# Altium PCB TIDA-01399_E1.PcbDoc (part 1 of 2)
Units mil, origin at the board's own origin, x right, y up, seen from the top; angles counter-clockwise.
Board outline 5937.01 x 6299.21 mil, 4 copper layers (Top Layer, MidLayer1, MidLayer2, Bottom Layer), stack 61.2 mil thick; 192 components, 137 nets, 411 pads, 57 vias.
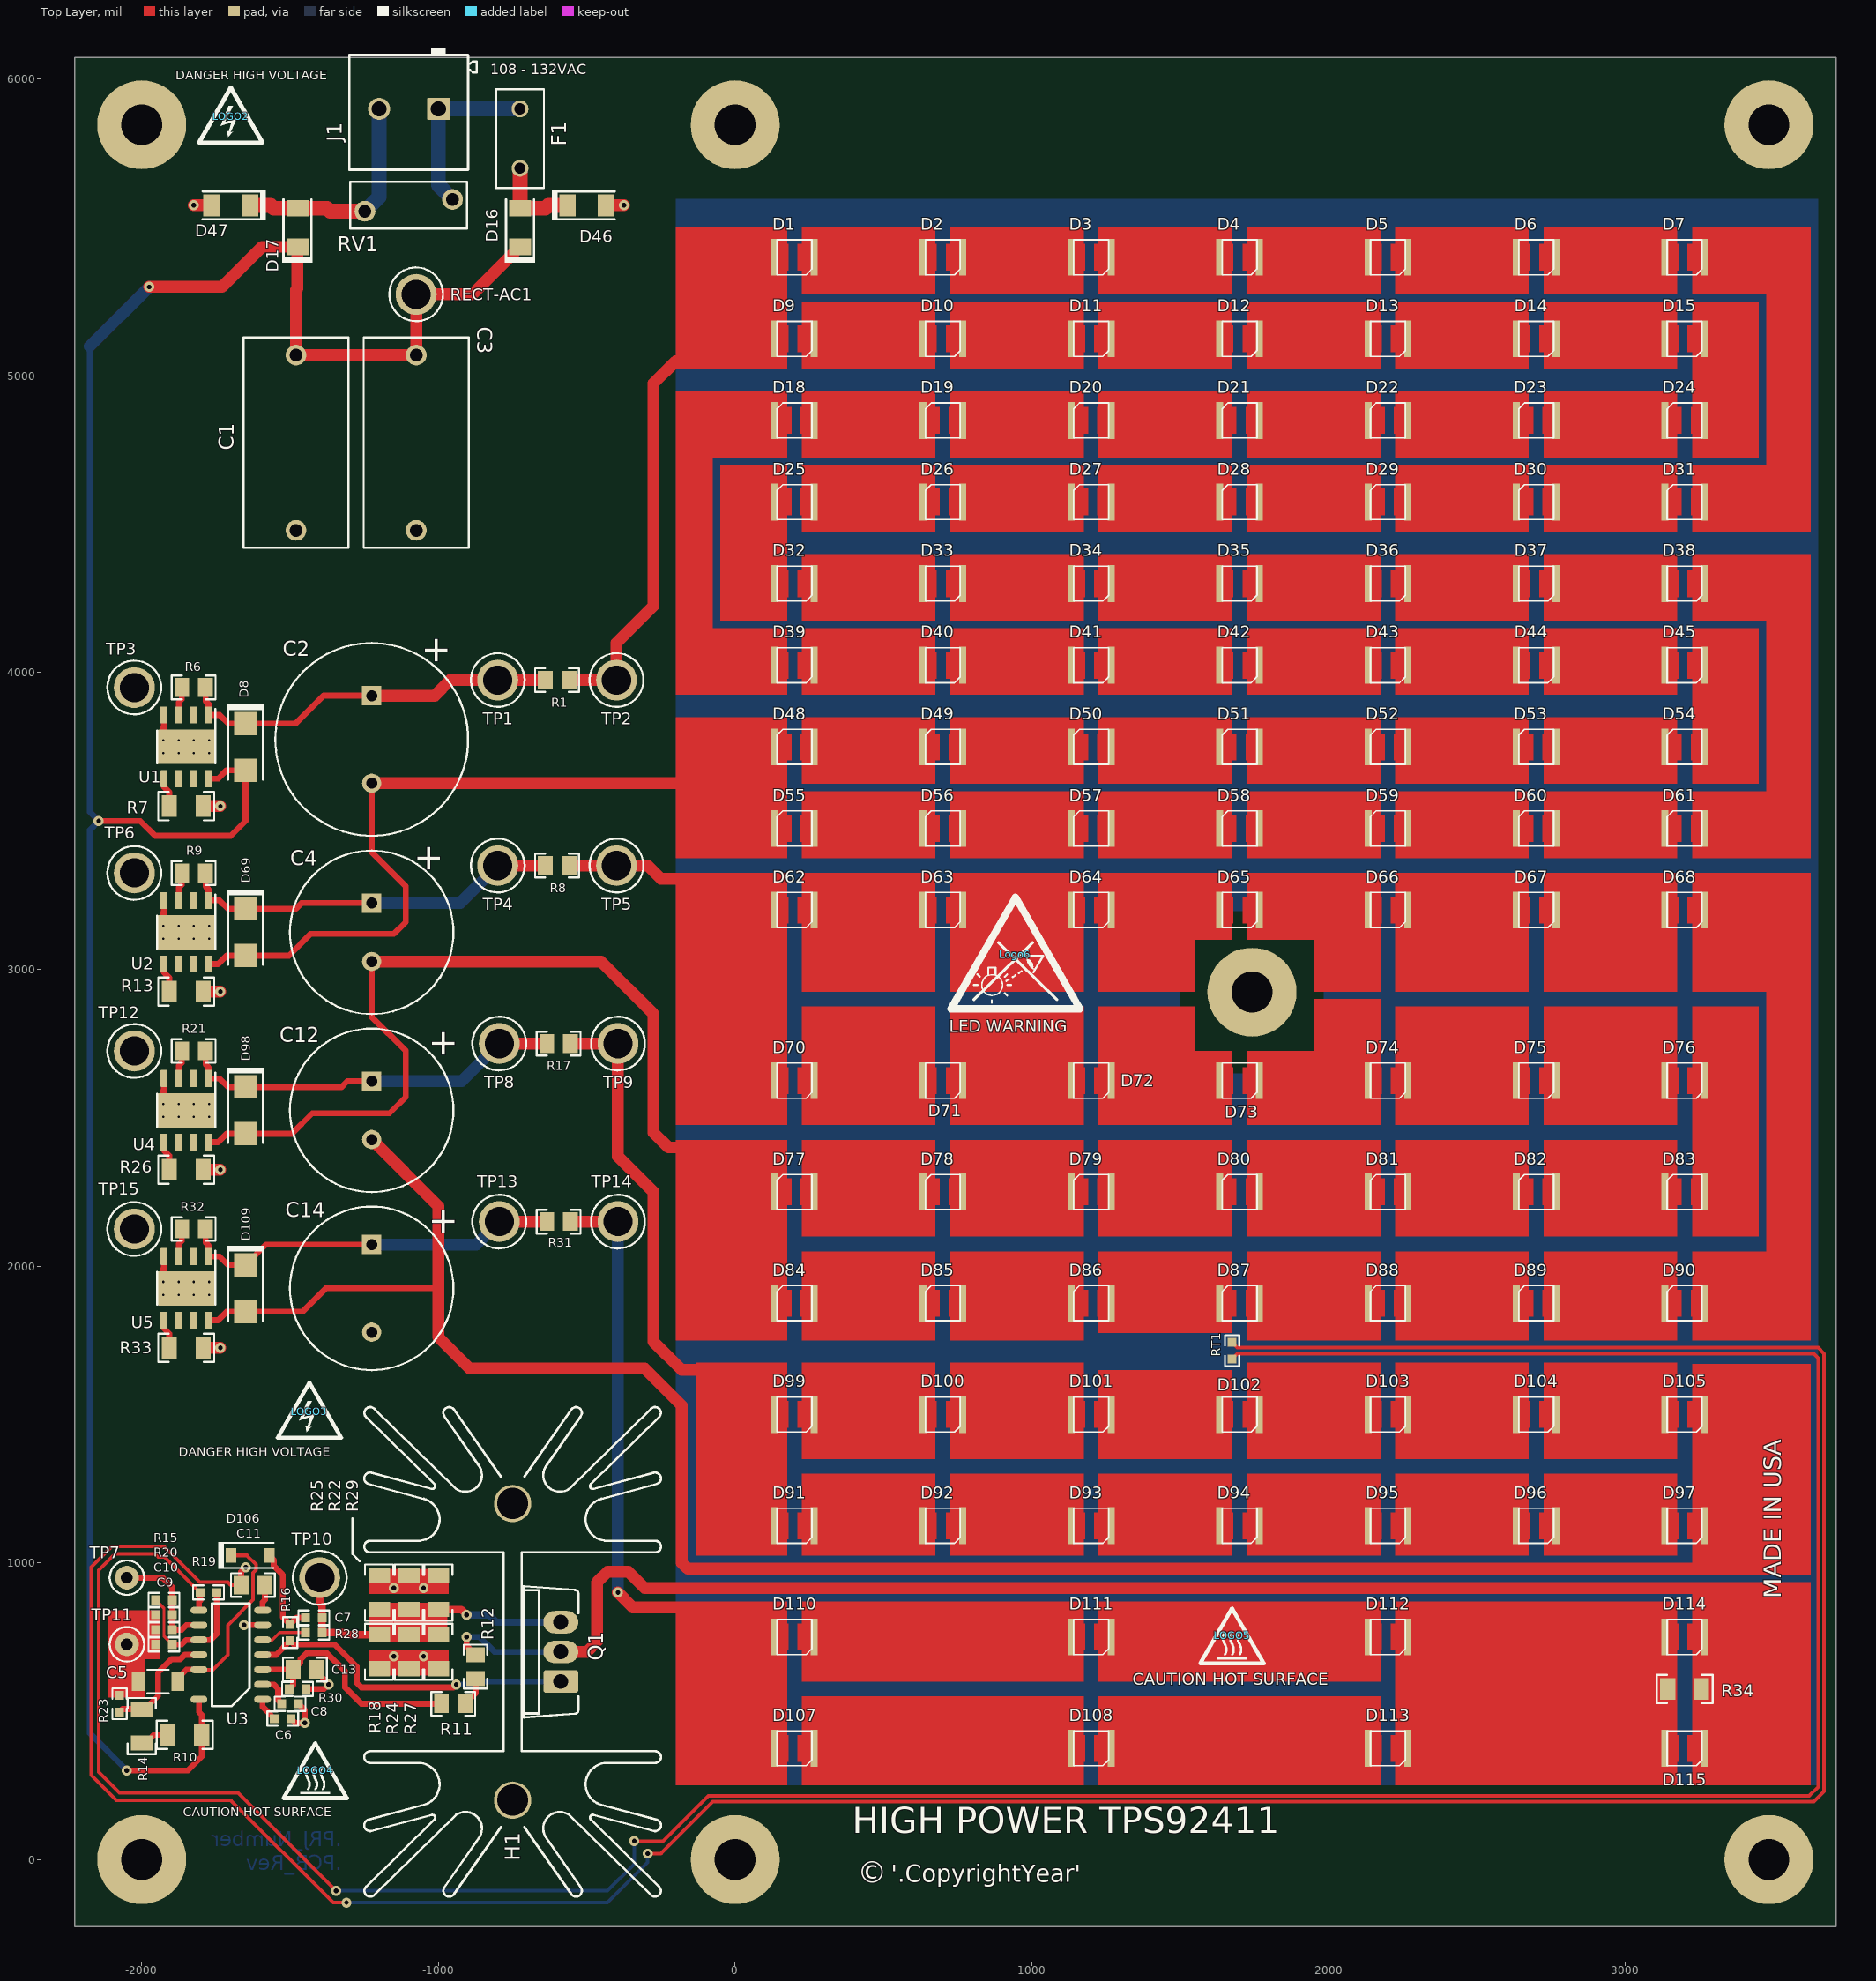
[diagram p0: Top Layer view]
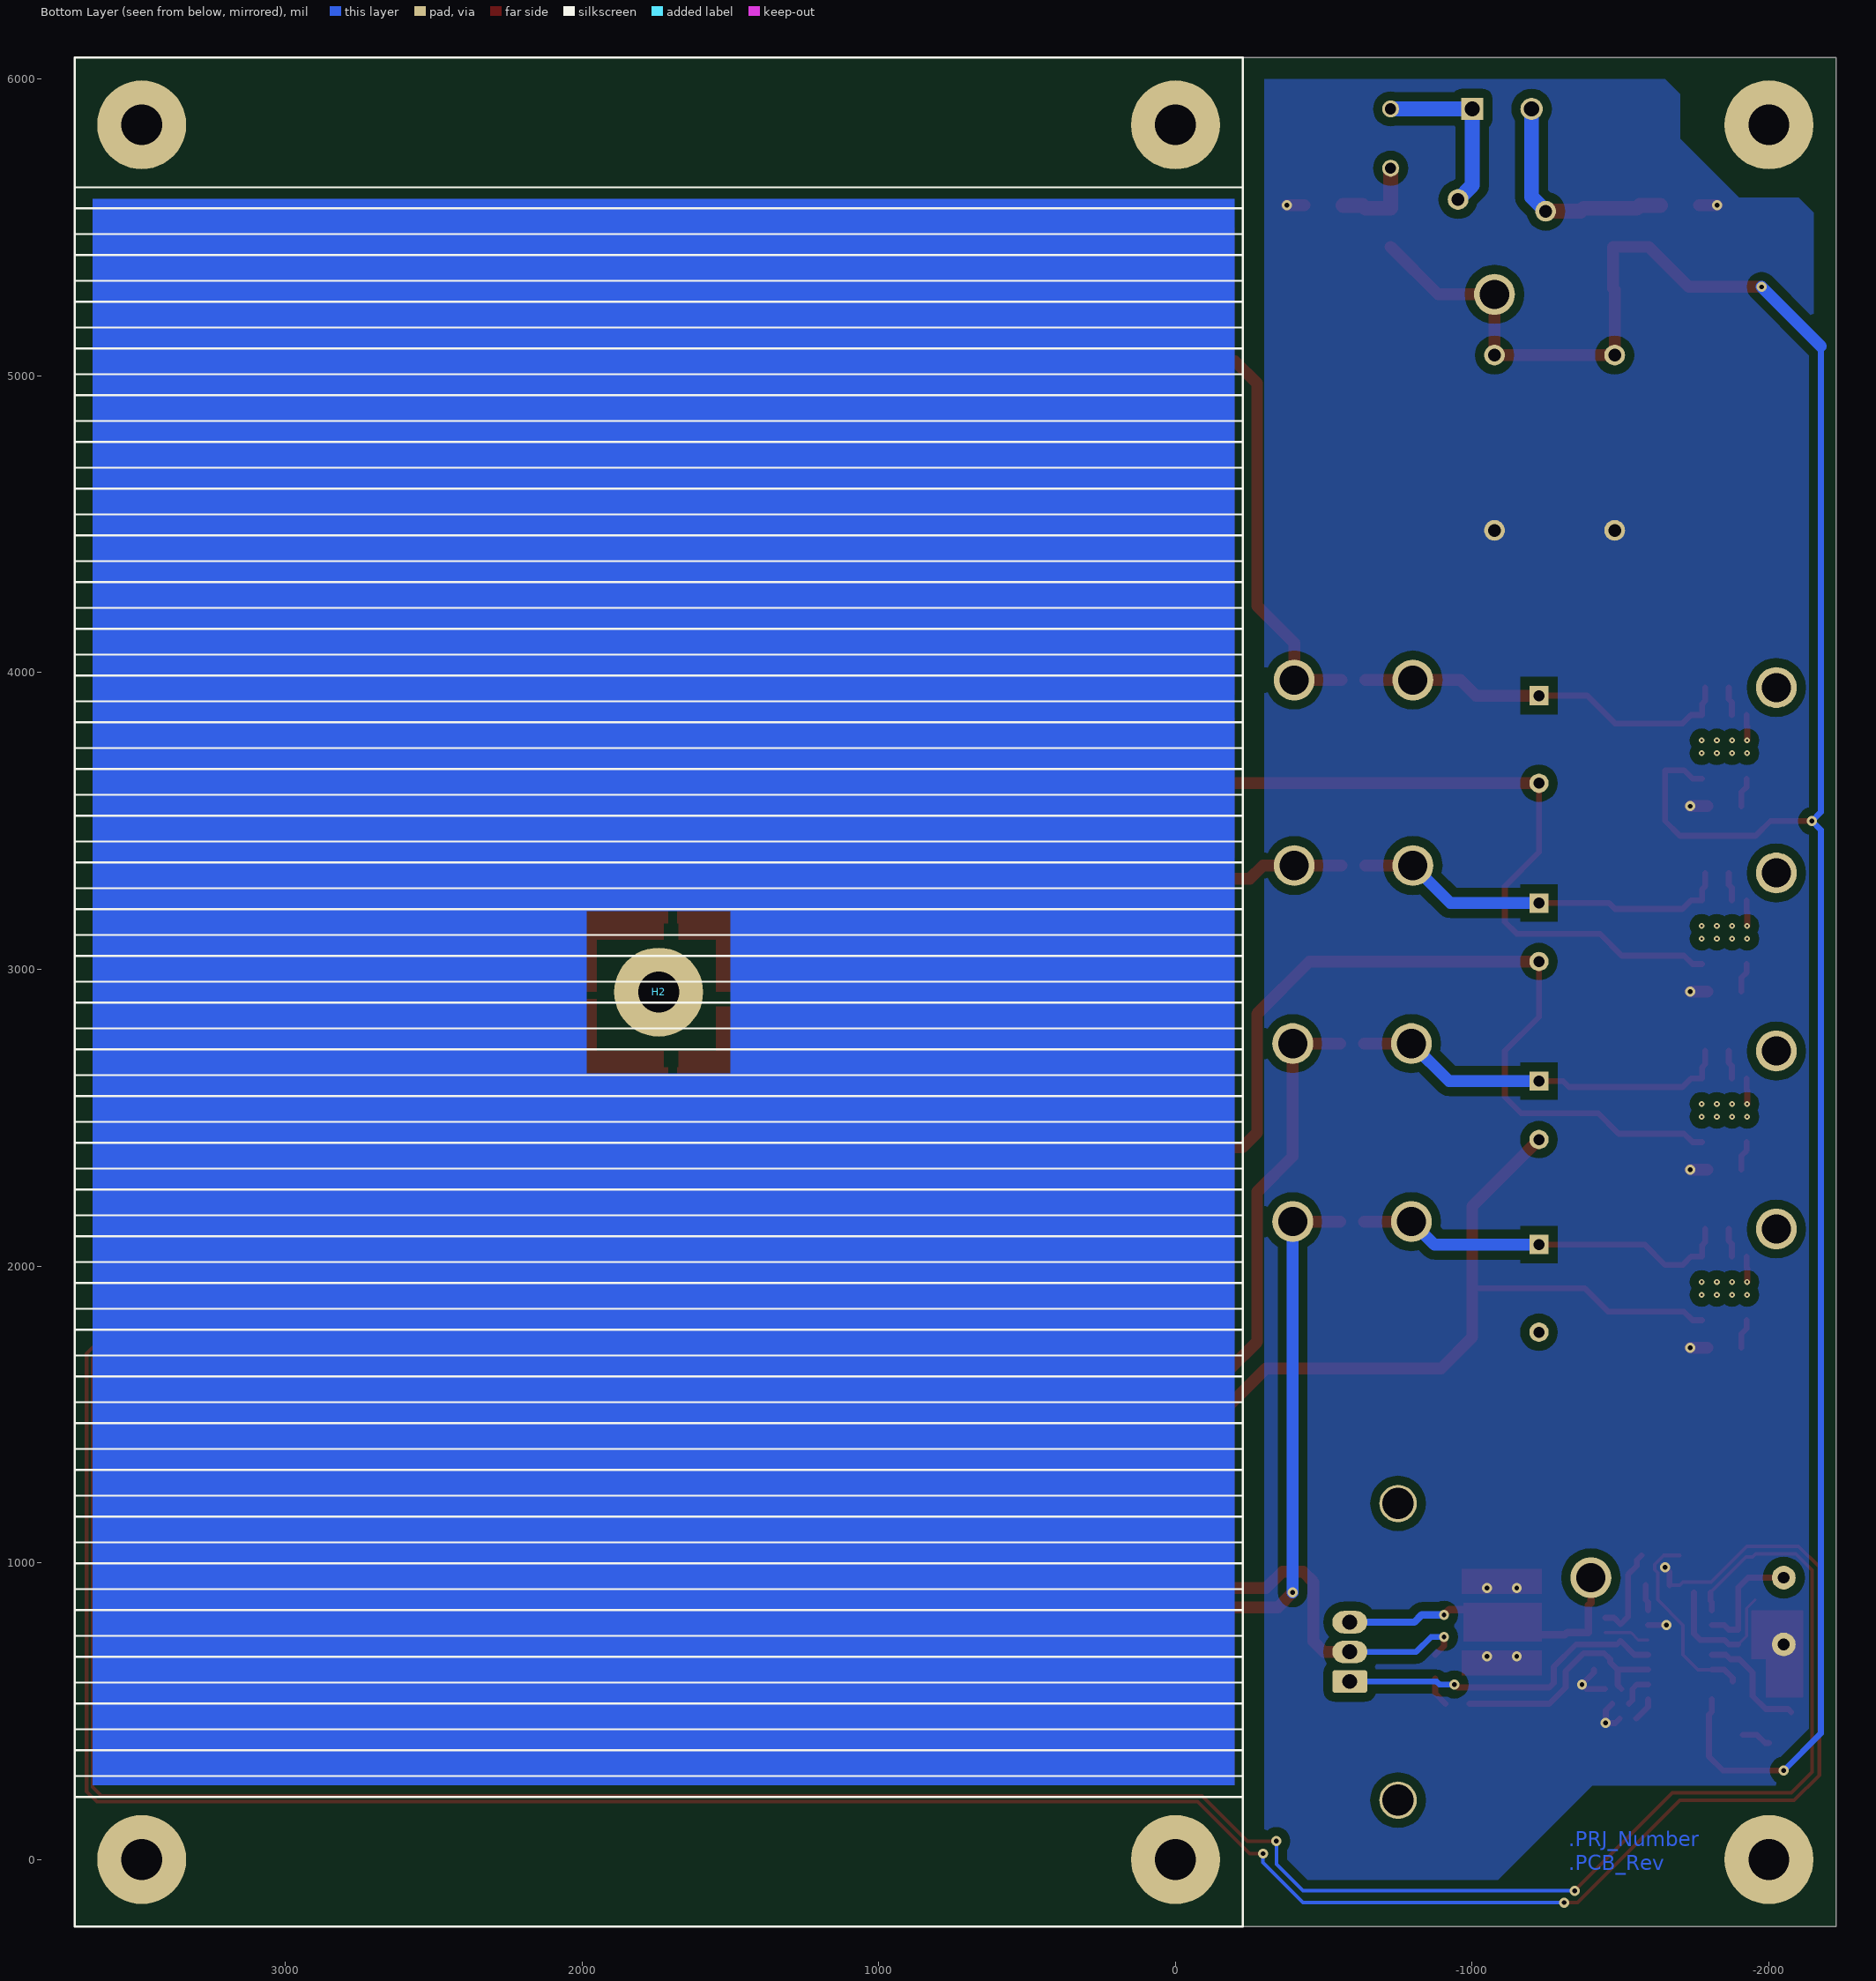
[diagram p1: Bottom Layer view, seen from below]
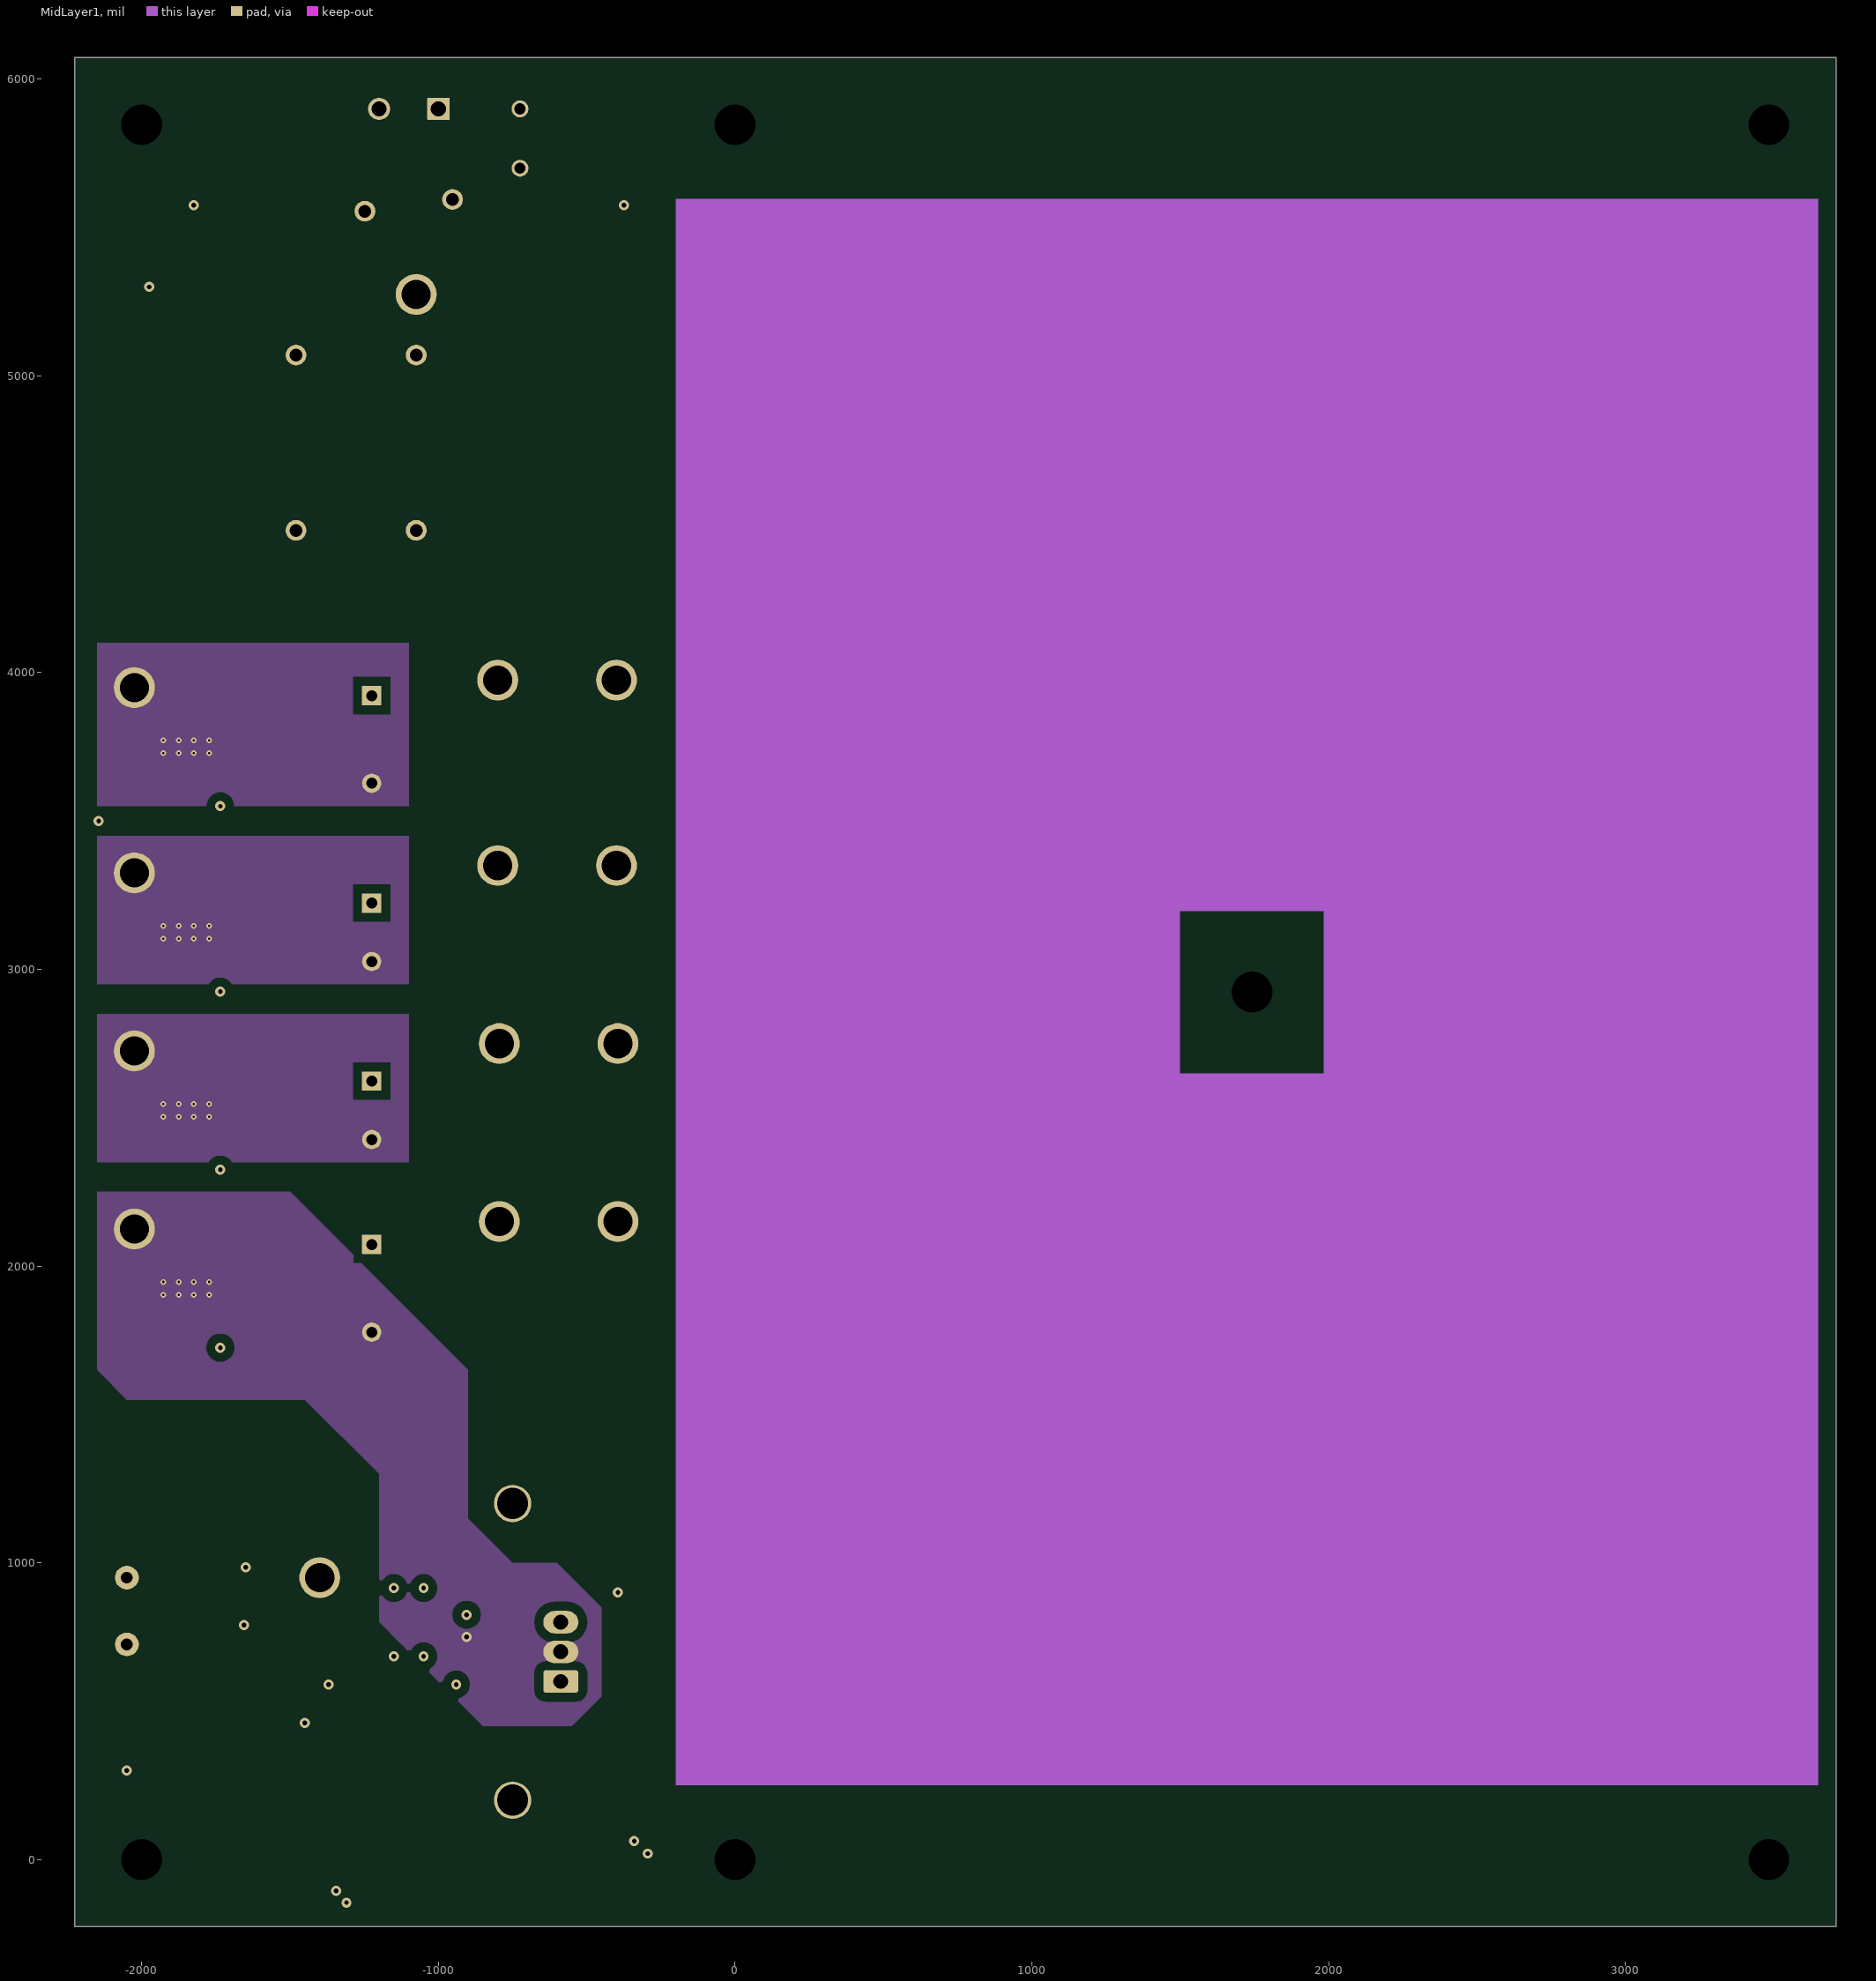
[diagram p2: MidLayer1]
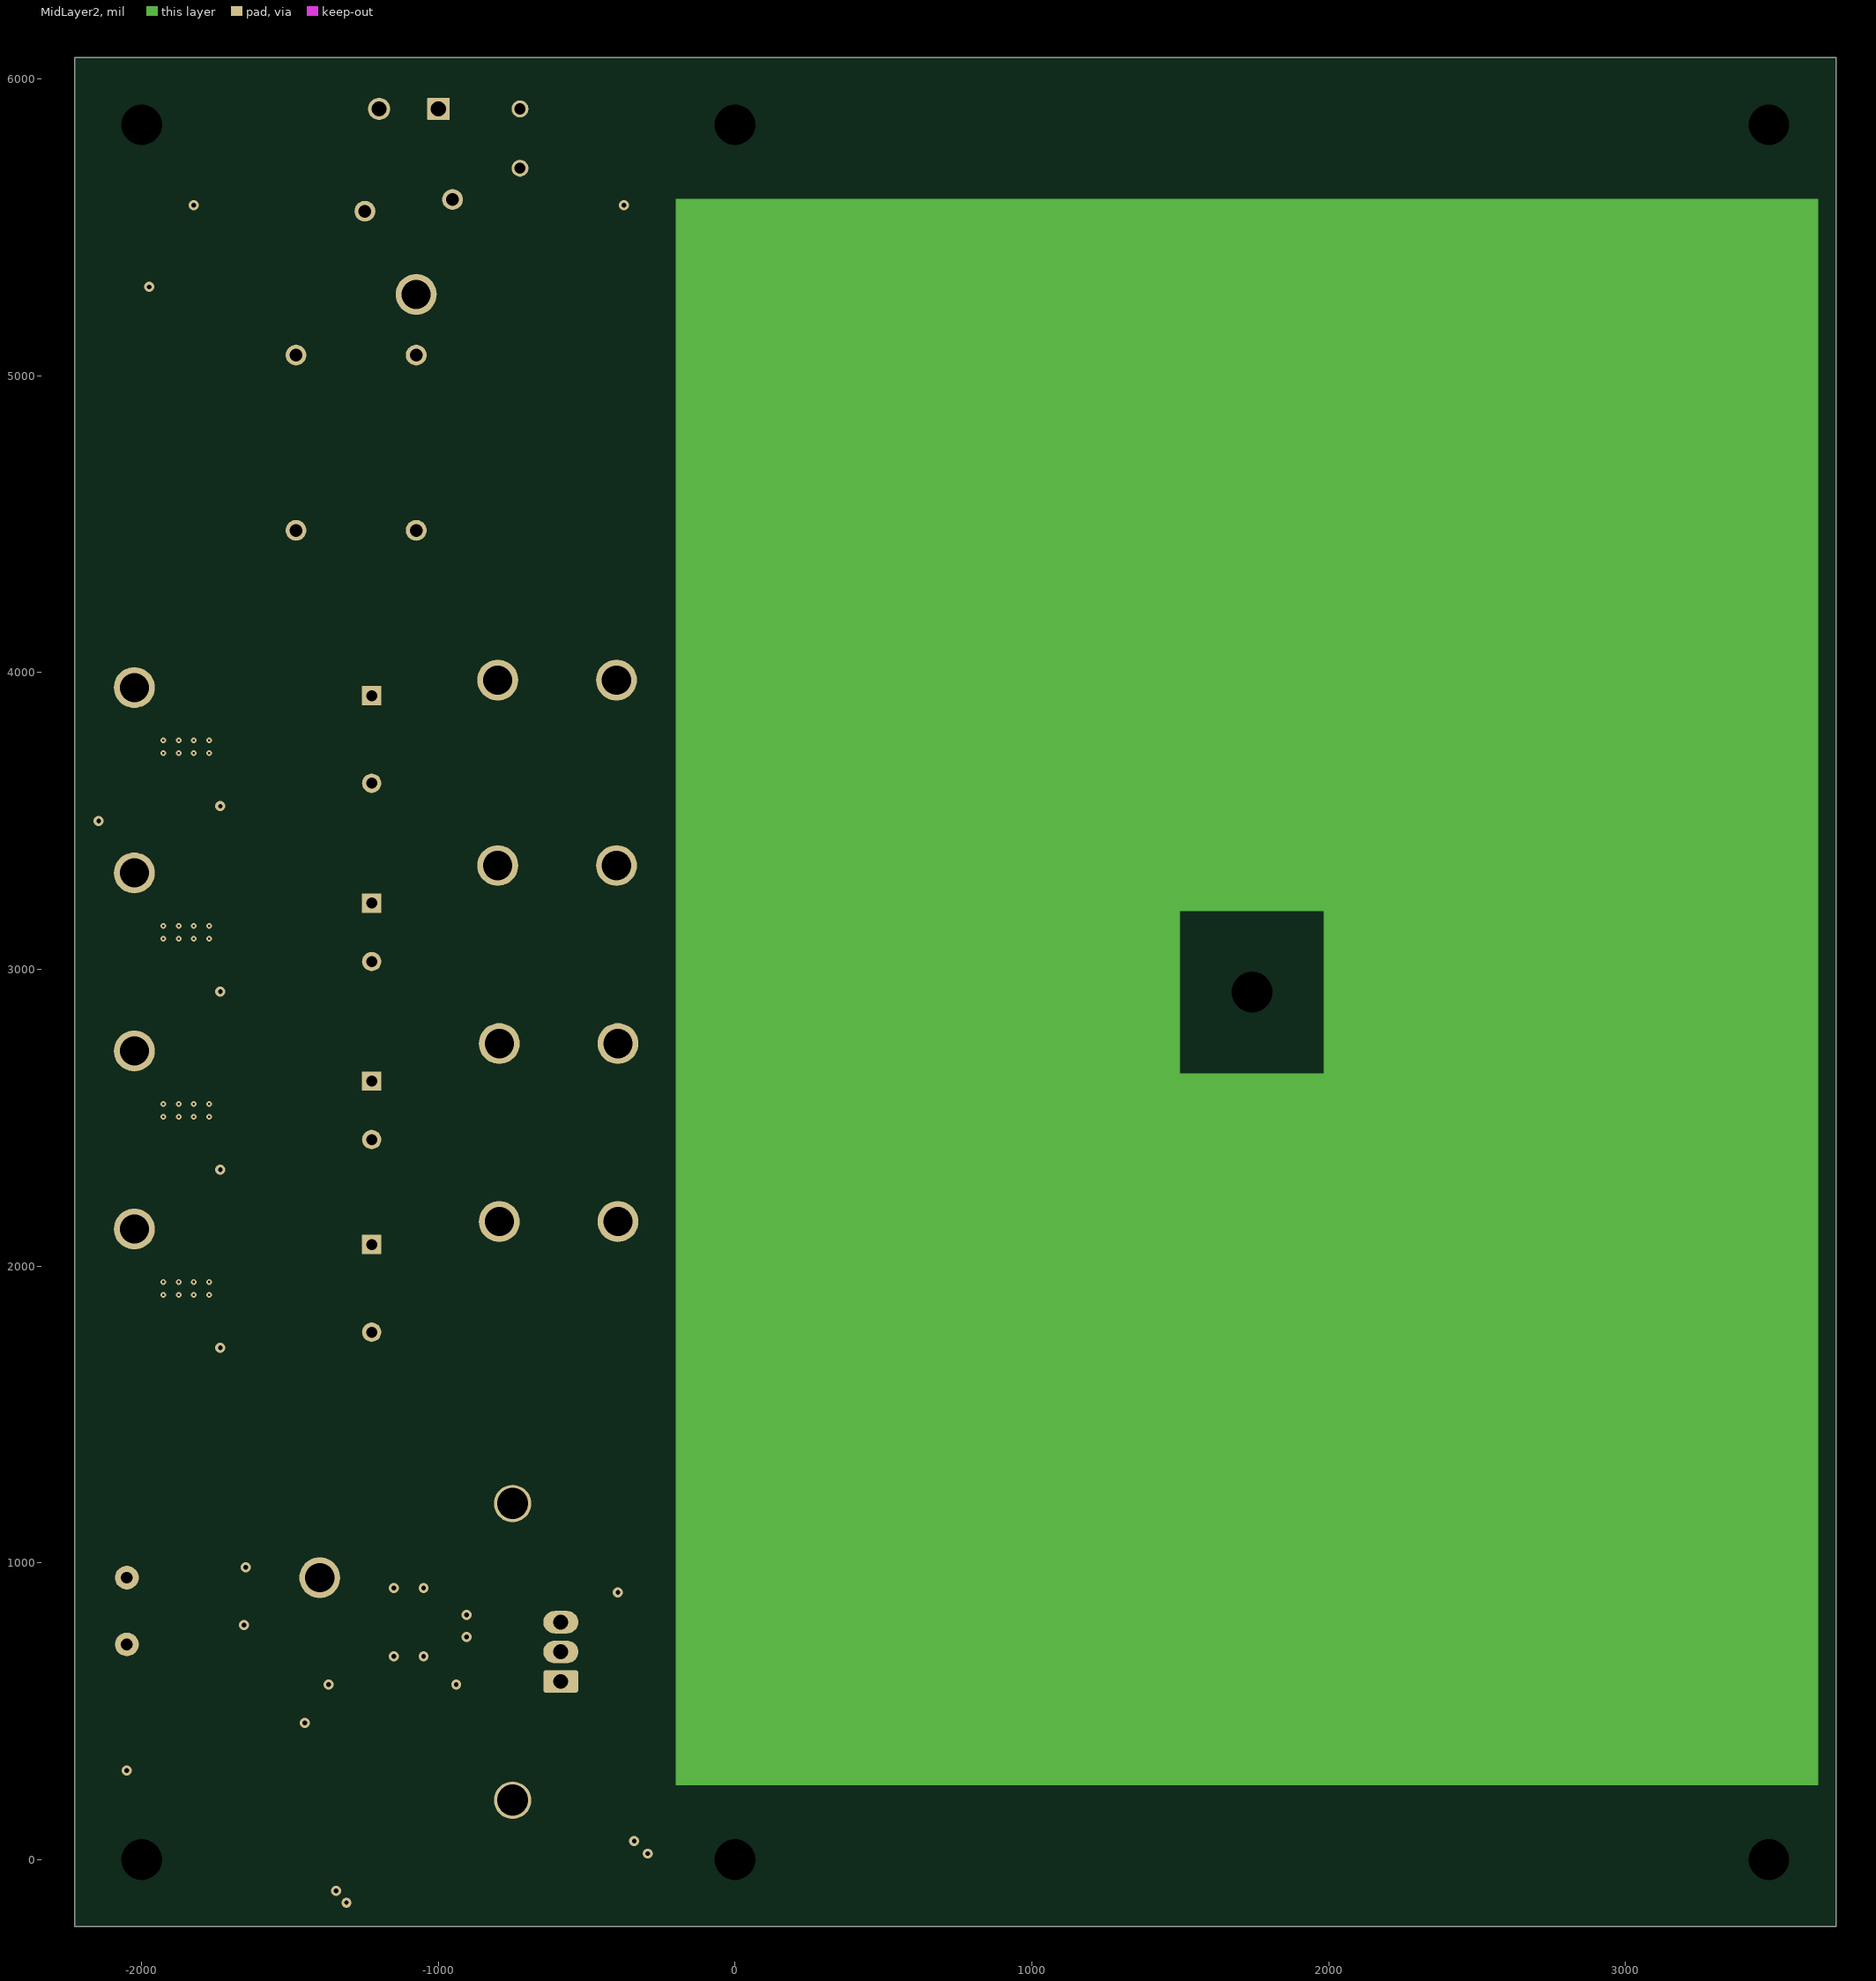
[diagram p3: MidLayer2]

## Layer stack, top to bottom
Top Solder: solder mask 0.4, Solder Resist, Dk 3.5
Top Layer: signal copper 1.4
Dielectric1: prepreg 8, FR-4, Dk 4.8
MidLayer1: signal copper 1.4
Dielectric2: core 39.6, FR-4, Dk 4.8
MidLayer2: signal copper 1.4
Dielectric3: prepreg 8, FR-4, Dk 4.8
Bottom Layer: signal copper 1.4
Bottom Solder: solder mask 0.4, Solder Resist, Dk 3.5

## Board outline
-2226.38,-226.38 3710.63,-226.38 3710.63,6072.83 -2226.38,6072.83

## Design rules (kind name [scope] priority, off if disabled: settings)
AcuteAngle AcuteAngle_DPAK [InNet('B1')] p1: minimum=1.00000000000000E+0001 checktracksonly=FALSE
AcuteAngle [All] p2: minimum=4.50000000000000E+0001 checktracksonly=FALSE
AssemblyTestPointUsage [All] p1: valid=2
Clearance Clearance_Polys [InPoly] p1: gap=30
Clearance Clearance_SOT23-5pads [HasFootprint('MF05A_L') vs HasFootprint('MF05A_L')] p2: gap=10
Clearance [All] p3: gap=8
ComponentClearance ComponentClearance_H1-Q1 [InComponent('H1') vs InComponent('Q1')] p1: gap=-1 collisioncheckmode=3 verticalgap=-1 showdistances=FALSE
ComponentClearance ComponentClearance_Logo6-D63_D64 [InComponent('Logo6') vs InComponent('D63') OR InComponent('D64')] p2: gap=-1 collisioncheckmode=3 verticalgap=-1 showdistances=FALSE
ComponentClearance ComponentClearance_SmallPassives [HasFootprint('0201*') or HasFootprint('0402*') or HasFootprint('0508') or HasFootprint('0603*') or HasFootprint('0612') or HasFootprint('0805*') or HasFootprint('0815*') or HasFootprint('0830*') or HasFootprint('1206*') or HasFootprint('1210*') or HasFootprint('1808*') or HasFootprint('1812*') or HasFootprint('1825*') or HasFootprint('2010*') or HasFootprint('2220*') or HasFootprint('2225*') or HasFootprint('2512*') or HasFootprint('2728*') or HasFootprint('3518*') vs HasFootprint('0201*') or HasFootprint('0402*') or HasFootprint('0508') or HasFootprint('0603*') or HasFootprint('0612') or HasFootprint('0805*') or HasFootprint('0815*') or HasFootprint('0830*') or HasFootprint('1206*') or HasFootprint('1210*') or HasFootprint('1808*') or HasFootprint('1812*') or HasFootprint('1825*') or HasFootprint('2010*') or HasFootprint('2220*') or HasFootprint('2225*') or HasFootprint('2512*') or HasFootprint('2728*') or HasFootprint('3518*')] p3: gap=5 collisioncheckmode=3 verticalgap=5 showdistances=FALSE
ComponentClearance [All] p4: gap=5 collisioncheckmode=3 verticalgap=5 showdistances=FALSE
DiffPairsRouting [All] p1: maxlimit=100 minlimit=10 mostfreqgap=10 toplayer_minwidth=15 toplayer_maxwidth=15 toplayer_prefwidth=15 midlayer1_minwidth=15 midlayer1_maxwidth=15 midlayer1_prefwidth=15 midlayer2_minwidth=15 midlayer2_maxwidth=15 midlayer2_prefwidth=15 bottomlayer_minwidth=15 bottomlayer_maxwidth=15 bottomlayer_prefwidth=15 maxuncoupledlength=1000
FabricationTestPointUsage TestPointUsage [All] p1: valid=2 allowmultiple=FALSE
FabricationTestpoint Testpoint [All] p1: side=3 testpointundercomponent=TRUE minsize=40 maxsize=100 preferedsize=60 minholesize=0 maxholesize=40 preferedholesize=32 testpointgrid=1 allowsidetop=TRUE allowsidebottom=TRUE usegrid=TRUE gridtolerance=0.01
FanoutControl Fanout_LCC [IsLCC] p1: bgadir=Out bgaviamode=Centered fanoutstyle=Auto fanoutdirection=Alternating viagrid=1 // Fanout_LCC (Default Rule)
FanoutControl Fanout_BGA [IsBGA] p2: bgadir=Out bgaviamode=Centered fanoutstyle=Auto fanoutdirection=Alternating viagrid=1 // Fanout_BGA (Default Rule)
FanoutControl Fanout_Default [All] p4: bgadir=Out bgaviamode=Centered fanoutstyle=Auto fanoutdirection=Alternating viagrid=1 // Fanout_Default (Default Rule)
FanoutControl Fanout_Small [(CompPinCount < 5)] p5: bgadir=Out bgaviamode=Centered fanoutstyle=Auto fanoutdirection=OutThenIn viagrid=1 // Fanout_Small (Default Rule)
Height [All] p1: minheight=0 maxheight=3000 prefheight=500
HoleSize [All] p1: absolutevalues=TRUE maxlimit=251 minlimit=7.87 maxpercent=80.000 minpercent=20.000
HoleToHoleClearance HoleToHoleClearance_LEDs [HasFootprint('LED_Cree_XLampMX-6S') vs HasFootprint('LED_Cree_XLampMX-6S')] p1: gap=-1 allowstackedmicrovias=TRUE
HoleToHoleClearance [All] p2: gap=10 allowstackedmicrovias=TRUE
MinimumAnnularRing [All] p1: minimumring=5.91
MinimumSolderMaskSliver MinimumSolderMaskSliver_LEDs [HasFootprint('LED_Cree_XLampMX-6S') vs HasFootprint('LED_Cree_XLampMX-6S')] p1: minsoldermaskwidth=-1
MinimumSolderMaskSliver MinimumSolderMaskSliver_Logo [InComponentClass('Logo') vs InComponentClass('Logo')] p2: minsoldermaskwidth=0.7
MinimumSolderMaskSliver [All] p3: minsoldermaskwidth=4
PlaneConnect [All] p1: planeconnectstyle=Relief reliefexpansion=10 reliefentries=4 reliefconductorwidth=10 reliefairgap=10
PolygonConnect [All] p1: connectstyle=Direct reliefconductorwidth=15 reliefentries=4 polygonreliefangle="90 Angle" airgapwidth=15
RoutingVias [All] p1: holewidth=16 width=34 viastyle="Through Hole" minholewidth=7.87 minwidth=19 maxholewidth=40 maxwidth=65
SMDToCorner [All] p1 off: distance=30000
ShortCircuit ShortCircuit_LEDs [IsRegion vs HasFootprint('LED_Cree_XLampMX-3AWT')] p1: allowed=TRUE
ShortCircuit [All] p2: allowed=FALSE
SilkToSilkClearance [All] p1: silktosilkclearance=5
SilkToSolderMaskClearance SilkToSolderMaskClearance_leds [HasFootprint('SPMWHT328FD5WAU0S0') vs (OnLayer('Top Overlay') AND HasFootprint('SPMWHT328FD5WAU0S0'))] p1: minsilkscreentomaskgap=-1 clearancetoexposedcopper=TRUE
SilkToSolderMaskClearance SilkToSolderMaskClearance_htsk_mtg_hole [HasFootprint('Htsk_HAMF10T') vs (OnLayer('Bottom Overlay') AND HasFootprint('Htsk_HAMF10T'))] p2: minsilkscreentomaskgap=-1 clearancetoexposedcopper=TRUE
SilkToSolderMaskClearance SilkscreenOverComponentPads [IsPad] p3: minsilkscreentomaskgap=5 clearancetoexposedcopper=TRUE
SolderMaskExpansion [All] p1: expansion=3
Width [All] p1: maxlimit=100 minlimit=6 preferedwidth=20 toplayer_minwidth=8 midlayer1_prefwidth=10 midlayer2_prefwidth=10 bottomlayer_minwidth=8 minimp=50.000000 maximp=50.000000 favimp=50.000000 checkconnectedcopper=TRUE
13 further rules are at their usual default settings.

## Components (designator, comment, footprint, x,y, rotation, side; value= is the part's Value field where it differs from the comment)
C1 "B32522C3155K" B32522C3155K -1480,4775 r270 top
C2 "UPW2A221MHD" UPW2A221MHD -1225,3775 r270 top
C3 "B32522C3155K" B32522C3155K -1075,4775 r270 top
C4 "UPW2A221MHD" UPW1H471MHD -1225,3125 r270 top
C5 "C3216X7R1E106M160AE" 1206_190 -1945,600.32 r180 top
C6 "GRM188R71C104KA01D" 0603_HV -1525,475 r180 top
C7 "GRM188R71C105KA12D" 0603_HV -1420,815 r180 top
C8 "GRM188R71C105KA12D" 0603_HV -1500,525 r180 top
C9 "GRM188R71C104KA01D" 0603_HV -1925,725 r180 top
C10 "GRM188R71H102KA01D" 0603_HV -1925,775 r180 top
C11 "GRM21BR71C475KA73L" 0805_HV -1625,925 r0 top
C12 "UPW1E102MHD" UPW1E102MHD -1225,2525 r270 top
C13 "0805YD106KAT2A" 0805_HV -1450,640 r0 top
C14 "UPW1C222MHD" UPW1C222MHD -1225,1925 r270 top
D1 "SPMWHT328FD5WAU0S0" SPMWHT328FD5WAU0S0 200,5400 r0 top
D2 "SPMWHT328FD5WAU0S0" SPMWHT328FD5WAU0S0 700,5400 r0 top
D3 "SPMWHT328FD5WAU0S0" SPMWHT328FD5WAU0S0 1200,5400 r0 top
D4 "SPMWHT328FD5WAU0S0" SPMWHT328FD5WAU0S0 1700,5400 r0 top
D5 "SPMWHT328FD5WAU0S0" SPMWHT328FD5WAU0S0 2200,5400 r0 top
D6 "SPMWHT328FD5WAU0S0" SPMWHT328FD5WAU0S0 2700,5400 r0 top
D7 "SPMWHT328FD5WAU0S0" SPMWHT328FD5WAU0S0 3200,5400 r0 top
D8 "ES1D-13-F" SMA -1650,3750 r270 top
D9 "SPMWHT328FD5WAU0S0" SPMWHT328FD5WAU0S0 200,5125 r0 top
D10 "SPMWHT328FD5WAU0S0" SPMWHT328FD5WAU0S0 700,5125 r0 top
D11 "SPMWHT328FD5WAU0S0" SPMWHT328FD5WAU0S0 1200,5125 r0 top
D12 "SPMWHT328FD5WAU0S0" SPMWHT328FD5WAU0S0 1700,5125 r0 top
D13 "SPMWHT328FD5WAU0S0" SPMWHT328FD5WAU0S0 2200,5125 r0 top
D14 "SPMWHT328FD5WAU0S0" SPMWHT328FD5WAU0S0 2700,5125 r0 top
D15 "SPMWHT328FD5WAU0S0" SPMWHT328FD5WAU0S0 3200,5125 r0 top
D16 "CGRM4007-G" MINI-SMA -725,5500 r90 top
D17 "CGRM4007-G" MINI-SMA -1475,5500 r90 top
D18 "SPMWHT328FD5WAU0S0" SPMWHT328FD5WAU0S0 200,4850 r180 top
D19 "SPMWHT328FD5WAU0S0" SPMWHT328FD5WAU0S0 700,4850 r180 top
D20 "SPMWHT328FD5WAU0S0" SPMWHT328FD5WAU0S0 1200,4850 r180 top
D21 "SPMWHT328FD5WAU0S0" SPMWHT328FD5WAU0S0 1700,4850 r180 top
D22 "SPMWHT328FD5WAU0S0" SPMWHT328FD5WAU0S0 2200,4850 r180 top
D23 "SPMWHT328FD5WAU0S0" SPMWHT328FD5WAU0S0 2700,4850 r180 top
D24 "SPMWHT328FD5WAU0S0" SPMWHT328FD5WAU0S0 3200,4850 r180 top
D25 "SPMWHT328FD5WAU0S0" SPMWHT328FD5WAU0S0 200,4575 r180 top
D26 "SPMWHT328FD5WAU0S0" SPMWHT328FD5WAU0S0 700,4575 r180 top
D27 "SPMWHT328FD5WAU0S0" SPMWHT328FD5WAU0S0 1200,4575 r180 top
D28 "SPMWHT328FD5WAU0S0" SPMWHT328FD5WAU0S0 1700,4575 r180 top
D29 "SPMWHT328FD5WAU0S0" SPMWHT328FD5WAU0S0 2200,4575 r180 top
D30 "SPMWHT328FD5WAU0S0" SPMWHT328FD5WAU0S0 2700,4575 r180 top
D31 "SPMWHT328FD5WAU0S0" SPMWHT328FD5WAU0S0 3200,4575 r180 top
D32 "SPMWHT328FD5WAU0S0" SPMWHT328FD5WAU0S0 200,4300 r0 top
D33 "SPMWHT328FD5WAU0S0" SPMWHT328FD5WAU0S0 700,4300 r0 top
D34 "SPMWHT328FD5WAU0S0" SPMWHT328FD5WAU0S0 1200,4300 r0 top
D35 "SPMWHT328FD5WAU0S0" SPMWHT328FD5WAU0S0 1700,4300 r0 top
D36 "SPMWHT328FD5WAU0S0" SPMWHT328FD5WAU0S0 2200,4300 r0 top
D37 "SPMWHT328FD5WAU0S0" SPMWHT328FD5WAU0S0 2700,4300 r0 top
D38 "SPMWHT328FD5WAU0S0" SPMWHT328FD5WAU0S0 3200,4300 r0 top
D39 "SPMWHT328FD5WAU0S0" SPMWHT328FD5WAU0S0 200,4025 r0 top
D40 "SPMWHT328FD5WAU0S0" SPMWHT328FD5WAU0S0 700,4025 r0 top
D41 "SPMWHT328FD5WAU0S0" SPMWHT328FD5WAU0S0 1200,4025 r0 top
D42 "SPMWHT328FD5WAU0S0" SPMWHT328FD5WAU0S0 1700,4025 r0 top
D43 "SPMWHT328FD5WAU0S0" SPMWHT328FD5WAU0S0 2200,4025 r0 top
D44 "SPMWHT328FD5WAU0S0" SPMWHT328FD5WAU0S0 2700,4025 r0 top
D45 "SPMWHT328FD5WAU0S0" SPMWHT328FD5WAU0S0 3200,4025 r0 top
D46 "CGRM4007-G" MINI-SMA -500,5575 r0 top
D47 "CGRM4007-G" MINI-SMA -1700,5575 r180 top
D48 "SPMWHT328FD5WAU0S0" SPMWHT328FD5WAU0S0 200,3750 r180 top
D49 "SPMWHT328FD5WAU0S0" SPMWHT328FD5WAU0S0 700,3750 r180 top
D50 "SPMWHT328FD5WAU0S0" SPMWHT328FD5WAU0S0 1200,3750 r180 top
D51 "SPMWHT328FD5WAU0S0" SPMWHT328FD5WAU0S0 1700,3750 r180 top
D52 "SPMWHT328FD5WAU0S0" SPMWHT328FD5WAU0S0 2200,3750 r180 top
D53 "SPMWHT328FD5WAU0S0" SPMWHT328FD5WAU0S0 2700,3750 r180 top
D54 "SPMWHT328FD5WAU0S0" SPMWHT328FD5WAU0S0 3200,3750 r180 top
D55 "SPMWHT328FD5WAU0S0" SPMWHT328FD5WAU0S0 200,3475 r180 top
D56 "SPMWHT328FD5WAU0S0" SPMWHT328FD5WAU0S0 700,3475 r180 top
D57 "SPMWHT328FD5WAU0S0" SPMWHT328FD5WAU0S0 1200,3475 r180 top
D58 "SPMWHT328FD5WAU0S0" SPMWHT328FD5WAU0S0 1700,3475 r180 top
D59 "SPMWHT328FD5WAU0S0" SPMWHT328FD5WAU0S0 2200,3475 r180 top
D60 "SPMWHT328FD5WAU0S0" SPMWHT328FD5WAU0S0 2700,3475 r180 top
D61 "SPMWHT328FD5WAU0S0" SPMWHT328FD5WAU0S0 3200,3475 r180 top
D62 "SPMWHT328FD5WAU0S0" SPMWHT328FD5WAU0S0 200,3200 r0 top
D63 "SPMWHT328FD5WAU0S0" SPMWHT328FD5WAU0S0 700,3200 r0 top
D64 "SPMWHT328FD5WAU0S0" SPMWHT328FD5WAU0S0 1200,3200 r0 top
D65 "SPMWHT328FD5WAU0S0" SPMWHT328FD5WAU0S0 1700,3200 r0 top
D66 "SPMWHT328FD5WAU0S0" SPMWHT328FD5WAU0S0 2200,3200 r0 top
D67 "SPMWHT328FD5WAU0S0" SPMWHT328FD5WAU0S0 2700,3200 r0 top
D68 "SPMWHT328FD5WAU0S0" SPMWHT328FD5WAU0S0 3200,3200 r0 top
D69 "ES1D-13-F" SMA -1650,3125 r270 top
D70 "SPMWHT328FD5WAU0S0" SPMWHT328FD5WAU0S0 200,2625 r0 top
D71 "SPMWHT328FD5WAU0S0" SPMWHT328FD5WAU0S0 700,2625 r0 top
D72 "SPMWHT328FD5WAU0S0" SPMWHT328FD5WAU0S0 1200,2625 r0 top
D73 "SPMWHT328FD5WAU0S0" SPMWHT328FD5WAU0S0 1700,2625 r0 top
D74 "SPMWHT328FD5WAU0S0" SPMWHT328FD5WAU0S0 2200,2625 r0 top
D75 "SPMWHT328FD5WAU0S0" SPMWHT328FD5WAU0S0 2700,2625 r0 top
D76 "SPMWHT328FD5WAU0S0" SPMWHT328FD5WAU0S0 3200,2625 r0 top
D77 "SPMWHT328FD5WAU0S0" SPMWHT328FD5WAU0S0 200,2250 r180 top
D78 "SPMWHT328FD5WAU0S0" SPMWHT328FD5WAU0S0 700,2250 r180 top
D79 "SPMWHT328FD5WAU0S0" SPMWHT328FD5WAU0S0 1200,2250 r180 top
D80 "SPMWHT328FD5WAU0S0" SPMWHT328FD5WAU0S0 1700,2250 r180 top
D81 "SPMWHT328FD5WAU0S0" SPMWHT328FD5WAU0S0 2200,2250 r180 top
D82 "SPMWHT328FD5WAU0S0" SPMWHT328FD5WAU0S0 2700,2250 r180 top
D83 "SPMWHT328FD5WAU0S0" SPMWHT328FD5WAU0S0 3200,2250 r180 top
D84 "SPMWHT328FD5WAU0S0" SPMWHT328FD5WAU0S0 200,1875 r180 top
D85 "SPMWHT328FD5WAU0S0" SPMWHT328FD5WAU0S0 700,1875 r180 top
D86 "SPMWHT328FD5WAU0S0" SPMWHT328FD5WAU0S0 1200,1875 r180 top
D87 "SPMWHT328FD5WAU0S0" SPMWHT328FD5WAU0S0 1700,1875 r180 top
D88 "SPMWHT328FD5WAU0S0" SPMWHT328FD5WAU0S0 2200,1875 r180 top
D89 "SPMWHT328FD5WAU0S0" SPMWHT328FD5WAU0S0 2700,1875 r180 top
D90 "SPMWHT328FD5WAU0S0" SPMWHT328FD5WAU0S0 3200,1875 r180 top
D91 "SPMWHT328FD5WAU0S0" SPMWHT328FD5WAU0S0 200,1125 r0 top
D92 "SPMWHT328FD5WAU0S0" SPMWHT328FD5WAU0S0 700,1125 r0 top
D93 "SPMWHT328FD5WAU0S0" SPMWHT328FD5WAU0S0 1200,1125 r0 top
D94 "SPMWHT328FD5WAU0S0" SPMWHT328FD5WAU0S0 1700,1125 r0 top
D95 "SPMWHT328FD5WAU0S0" SPMWHT328FD5WAU0S0 2200,1125 r0 top
D96 "SPMWHT328FD5WAU0S0" SPMWHT328FD5WAU0S0 2700,1125 r0 top
D97 "SPMWHT328FD5WAU0S0" SPMWHT328FD5WAU0S0 3200,1125 r0 top
D98 "ES1D-13-F" SMA -1650,2525 r270 top
D99 "SPMWHT328FD5WAU0S0" SPMWHT328FD5WAU0S0 200,1500 r0 top
D100 "SPMWHT328FD5WAU0S0" SPMWHT328FD5WAU0S0 700,1500 r0 top
D101 "SPMWHT328FD5WAU0S0" SPMWHT328FD5WAU0S0 1200,1500 r0 top
D102 "SPMWHT328FD5WAU0S0" SPMWHT328FD5WAU0S0 1700,1500 r0 top
D103 "SPMWHT328FD5WAU0S0" SPMWHT328FD5WAU0S0 2200,1500 r0 top
D104 "SPMWHT328FD5WAU0S0" SPMWHT328FD5WAU0S0 2700,1500 r0 top
D105 "SPMWHT328FD5WAU0S0" SPMWHT328FD5WAU0S0 3200,1500 r0 top
D106 "MMSD4148T1G" SOD-123 -1635,1025 r0 top
D107 "SPMWHT328FD5WAU0S0" SPMWHT328FD5WAU0S0 200,375 r0 top
D108 "SPMWHT328FD5WAU0S0" SPMWHT328FD5WAU0S0 1200,375 r0 top
D109 "ES1D-13-F" SMA -1650,1925 r270 top
D110 "SPMWHT328FD5WAU0S0" SPMWHT328FD5WAU0S0 200,750 r0 top
D111 "SPMWHT328FD5WAU0S0" SPMWHT328FD5WAU0S0 1200,750 r0 top
D112 "SPMWHT328FD5WAU0S0" SPMWHT328FD5WAU0S0 2200,750 r0 top
D113 "SPMWHT328FD5WAU0S0" SPMWHT328FD5WAU0S0 2200,375 r0 top
D114 "SPMWHT328FD5WAU0S0" SPMWHT328FD5WAU0S0 3200,750 r0 top
D115 "SPMWHT328FD5WAU0S0" SPMWHT328FD5WAU0S0 3200,375 r0 top
F1 "RST 2" FUSE_RST -725,5800 r90 top
H1 "530002B02500G" Aavid_530002B02500G -750,700 r90 top locked
H2 "HAMF10T" Htsk_HAMF10T 1742.13,2923.23 r90 bottom locked
J1 "1715721" PhoenixContact_1715721 -1100,5900 r180 top
LOGO2 "DANGER HIGH VOLTAGE" IEC_HighVoltage_Small -1700,5874.08 r0 top
LOGO3 "DANGER HIGH VOLTAGE" IEC_HighVoltage_Small -1435,1510 r0 top
LOGO4 "CAUTION HOT SURFACE" IEC_HotSurface_Small -1415,300 r0 top
LOGO5 "CAUTION HOT SURFACE" IEC_HotSurface_Small 1675,753.94 r0 top
Logo6 "LED WARNING" LED_Warning 945,3050 r0 top (schematic designator LOGO6)
Q1 "AOT11S60L" TO-220AB -587.5,700 r90 top locked
R1 "CSR0805FKR250" 0805_HV -600,3975 r0 top
R6 "CRCW08051M50FKEA" 0805_HV -1825,3950 r0 top
R7 "CRCW1206806KFKEA" 1206 -1850,3550 r180 top
R8 "CSR0805FKR250" 0805_HV -600,3350 r0 top
R9 "CRCW08051M40FKEA" 0805_HV -1825,3325 r0 top
R10 "CRCW12061M00FKEA" 1206 -1855,420 r180 top
R11 "CRCW08052M00FKEA" 0805_HV -950,525 r0 top
R12 "CRCW08052M00FKEA" 0805_HV -875,650 r90 top
R13 "CRCW1206806KFKEA" 1206 -1850,2925 r180 top
R14 "CRCW12061M00FKEA" 1206 -2000,450 r270 top
R15 "CRCW0603200KFKEA" 0603_HV -1925,875 r180 top
R16 "CRCW060310R0FKEA" 0603_HV -1500,765 r270 top
R17 "CSR0805FKR250" 0805_HV -595,2750 r0 top
R18 "CRCW120618R2FKEA" 1206 -1200,700 r270 top
R19 "CRCW060330K1FKEA" 0603_HV -1775,900 r0 top
R20 "DNP" 0603_HV -1925,825 r0 top
R21 "CRCW08051M24FKEA" 0805_HV -1825,2725 r0 top
R22 "CRCW120618R2FKEA" 1206 -1100,900 r90 top
R23 "CRCW060330K1FKEA" 0603_HV -2075,525 r270 top
R24 "CRCW120618R2FKEA" 1206 -1100,700 r270 top
R25 "CRCW120618R2FKEA" 1206 -1200,900 r90 top
R26 "CRCW1206806KFKEA" 1206 -1850,2325 r180 top
R27 "CRCW120618R2FKEA" 1206 -1000,700 r270 top
R28 "CRCW060354K9FKEA" 0603_HV -1420,765 r0 top
R29 "CRCW120618R2FKEA" 1206 -1000,900 r90 top
R30 "CRCW0603121KFKEA" 0603_HV -1475,575 r180 top
R31 "CSR0805FKR250" 0805_HV -595,2150 r0 top
R32 "CRCW0805976KFKEA" 0805_HV -1825,2125 r0 top
R33 "CRCW1206806KFKEA" 1206 -1850,1725 r180 top
R34 "DNP" 1206 3200,575 r180 top
RECT-AC1 "Suggest using a net name here" Keystone1502-2 -1075,5275 r180 top
RT1 "NCP18WM474E03RB" 0603_HV 1675,1715 r270 top
RV1 "MOV-10D241K" MOV-10D241K -1100,5575 r0 top
TP1 "Suggest using a net name here" Keystone1502-2 -800,3975 r0 top
TP2 "Suggest using a net name here" Keystone1502-2 -400,3975 r0 top
TP3 "Suggest using a net name here" Keystone1502-2 -2025,3950 r0 top
TP4 "Suggest using a net name here" Keystone1502-2 -800,3350 r0 top
TP5 "Suggest using a net name here" Keystone1502-2 -400,3350 r0 top
TP6 "Suggest using a net name here" Keystone1502-2 -2025,3325 r0 top
TP7 "5002" Keystone5002 -2050,950 r0 top
TP8 "Suggest using a net name here" Keystone1502-2 -795,2750 r0 top
TP9 "Suggest using a net name here" Keystone1502-2 -395,2750 r0 top
TP10 "Suggest using a net name here" Keystone1502-2 -1400,950 r0 top
TP11 "5001" Keystone5001 -2050,725 r0 top
TP12 "Suggest using a net name here" Keystone1502-2 -2025,2725 r0 top
TP13 "Suggest using a net name here" Keystone1502-2 -795,2150 r180 top
TP14 "Suggest using a net name here" Keystone1502-2 -395,2150 r180 top
TP15 "Suggest using a net name here" Keystone1502-2 -2025,2125 r180 top
U1 "TPS92411DDAR" DDA0008E_N -1850,3750 r270 top
U2 "TPS92411DDAR" DDA0008E_N -1850,3125 r270 top
U3 "TPS92410DR" D0013A_N -1700,690 r180 top
U4 "TPS92411DDAR" DDA0008E_N -1850,2525 r270 top
U5 "TPS92411DDAR" DDA0008E_N -1850,1925 r270 top

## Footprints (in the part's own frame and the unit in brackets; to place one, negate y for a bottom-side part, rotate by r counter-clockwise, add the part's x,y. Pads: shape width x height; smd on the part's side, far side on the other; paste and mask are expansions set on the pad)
0603_HV [mil] "Ernesto recommended land pattern.  26 mil between pads."
  rect 30x30 smd: 1(-28,0) 2(28,0)
  silkscreen extent -52,-24 52,24, body extent -34,-19 34,19, height 39
0805_HV [mil] "0805 with 30mil clearance between pads"
  rect 50x63 smd: 1(-40,0) 2(40,0)
  silkscreen extent -74,-40 74,40, body extent -43,-29 43,29, height 57
1206 [mm] "1206 from SM-752 data"
  rect 1.3x1.85 smd: 1(-1.45,0) 2(1.45,0)
  silkscreen extent -2.4,-1.21 2.4,1.21, body extent -1.7,-0.9 1.7,0.9, height 1.35
1206_190 [mm] "1206_190"
  rect 1.1x1.6 smd: 1(-1.7,0) 2(1.7,0)
  silkscreen extent -0.9,-1 0.9,1, body extent -1.75,-0.95 1.75,0.95, height 1.9
Aavid_530002B02500G [mm] "TH, 2-Leads, Body 41.91x25.4mm, Pin Spacing 25.4mm"
  round 3.2 hole 2.67: 1(-12.7,0) 2(12.7,0)
  silkscreen extent -20.95,-12.7 20.95,12.7, body extent -20.95,-12.7 20.96,12.7, height 63.5
B32522C3155K [mil] "Cap EPCOS P/N B32522C3155K"
  round 70 hole 43: 1(-295.28,0) 2(295.28,0)
  silkscreen extent -354,-177 354,177, body extent -354,-177 354,177, height 689
D0013A_N [mm] "SOIC, 14-Leads, Pin#13 removed, Body 8.7x3.9mm, Pitch 1.27mm, IPC Medium Density"
  oval 1.45x0.6 smd: 1(-2.725,3.81) 2(-2.725,2.54) 3(-2.725,1.27) 4(-2.725,0) 5(-2.725,-1.27) 6(-2.725,-2.54) 7(-2.725,-3.81) 8(2.725,-3.81) 9(2.725,-2.54) 10(2.725,-1.27) 11(2.725,0) 12(2.725,1.27) 14(2.725,3.81)
  silkscreen extent -1.6,-4.4 1.6,4.4, body extent -3.01,-4.32 3.01,4.33, height 1.75
DDA0008E_N [mm]
  rrect17% 1.45x0.6 smd: 1(-2.725,1.905) 2(-2.725,0.635) 3(-2.725,-0.635) 4(-2.725,-1.905) 5(2.725,-1.905) 6(2.725,-0.635) 7(2.725,0.635) 8(2.725,1.905)
  rrect7% 2.95x4.9 smd paste-1.5 mask-1.5: 9(0,0)
  rrect4% 2.4x3.1 on Top Paste: 9(0,0)
  rrect4% 2.4x3.1 on Top Solder: 9(0,0)
  silkscreen extent -3.22,-2.5 1.4,2.5, body extent -3,-2.45 3,2.45, height 1.57
FUSE_RST [mm] "Bel Fuse RST series May2012D"
  round 1.45 hole 0.95: 1(-2.54,0) 2(2.54,0)
  silkscreen extent -4.23,-2.05 4.23,2.05, body extent -4.22,-2.05 4.23,2.05, height 7.9
Htsk_HAMF10T [mm]
  round 7.62 / inner round 0 / far side round 7.62 hole 3.5 unplated: 0(-74.25,-44.25) 0(-74.25,44.25) 0(0,0) 0(74.25,-44.25) 0(74.25,44.25)
  silkscreen extent -80,-50 80,50, body extent -80,-50 80,50, height 33.4
IEC_HighVoltage_Small [mil]
  silkscreen extent -107,-88 107,97
IEC_HotSurface_Small [mil]
  silkscreen extent -107,-93 107,92
Keystone1502-2 [mm] "Double Turret"
  round 3.5 hole 2.5: 1(0,0)
  silkscreen extent -2.3,-2.3 2.3,2.3, body extent -1.6,-1.6 1.59,1.6, height 5.62
Keystone5001 [mil] "For Keystone 500x miniature loop terminals"
  round 80 hole 40: 1(0,0)
  silkscreen extent -58,-58 58,58, body extent -49,-49 49,49, height 182
Keystone5002 [mil] "For Keystone 500x miniature loop terminals"
  round 80 hole 40: 1(0,0)
  silkscreen extent -58,-58 58,58, body extent -49,-49 49,49, height 182
LED_Warning [mil]
  silkscreen extent -217,-182 217,193
MINI-SMA [mm] "COMCHIP"
  rect 1.4x1.9 smd: 1(-1.65,0) 2(1.65,0)
  silkscreen extent -3,-1.3 2.4,1.3, body extent -1.95,-0.9 1.95,0.9, height 1.7
MOV-10D241K [mil] "Bourns MOV P/N MOV-10D241K"
  round 70 hole 43: 1(-147.64,-19.69) 2(147.64,19.69)
  silkscreen extent -197,-79 197,79, body extent -246,-79 246,79, height 620
PhoenixContact_1715721 [mm] "Phoenix Contact 1715721 used on LM3445 design from Longmont"
  rrect5% 1.905x1.905 hole 1.3: 1(-2.54,0)
  round 1.9 hole 1.3: 2(2.54,0)
  silkscreen extent -5.82,-5.25 5.08,5.2, body extent -5.82,-4.6 5.08,5.2, height 14.2
SMA [mm] "Molded Diode, 2-Leads, Body 4.3x2.6mm, IPC Medium Density, based on OnSemi component dimensions and land pattern"
  rect 2x2 smd: 1(-2,0) 2(2,0)
  silkscreen extent -3.66,-1.57 2.79,1.57, body extent -2.6,-1.3 2.6,1.3, height 2.42
SOD-123 [mm] "On Semi recommended land pattern"
  rect 0.915x1.22 smd: 1(-1.637,0) 2(1.637,0)
  silkscreen extent -2.74,-1.17 2.03,1.17, body extent -1.93,-0.9 1.93,0.9, height 1.35
SPMWHT328FD5WAU0S0 [mm] "Samsung LED P/N SPMWHT328FD5WAU0S0"
  rect 0.6x3.15 smd: 1(-1.7,0) 2(1.7,0)
  Top Layer region: 1.8,1.15 0.25,1.15 0.25,-1.15 1.8,-1.15
  Top Layer region: -1.8,-1.15 -0.52,-1.15 -0.52,1.15 -1.8,1.15
  silkscreen extent -1.5,-1.5 1.5,1.5, body extent -1.5,-1.5 1.5,1.5, height 0.65
TO-220AB [mil] "Copied from Altium's version of TO3B"
  rrect25% 76x118.11 hole 50: 1(-100,0)
  oval 76x118.11 hole 50: 2(0,0) 3(100,0)
  silkscreen extent -221,-59 221,126, body extent -221,-59 221,126, height 765
UPW1C222MHD [mil] "12.5Dx25T-5mmLS"
  rect 65x65 hole 37: 1(-147.64,0)
  round 65 hole 37: 2(147.64,0)
  silkscreen extent -276,-276 276,276, body extent -276,-276 276,276, height 1067
UPW1E102MHD [mil] "12.5Dx20T-5mmLS"
  rect 65x65 hole 37: 1(-98.43,0)
  round 65 hole 37: 2(98.43,0)
  silkscreen extent -276,-276 276,276, body extent -276,-276 276,276, height 870
UPW1H471MHD [mil] "12.5Dx20T-5mmLS"
  rect 65x65 hole 37: 1(-98.43,0)
  round 65 hole 37: 2(98.43,0)
  silkscreen extent -276,-276 276,276, body extent -276,-276 276,276, height 870
UPW2A221MHD [mil] "16Dx25T-7.5mm LS"
  rect 65x65 hole 37: 1(-147.64,0)
  round 65 hole 37: 2(147.64,0)
  silkscreen extent -325,-325 325,325, body extent -325,-325 325,325, height 1067

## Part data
C1 C3: library part Capacitor, "CAP, Film, 1.5uF, 160VAC, 250VDC, 10%, Radial"
C2: "CAP, AL, 220µF, 100V, +/- 20%, Radial"
C4: "CAP, AL, 470µF, 50V, +/- 20%, Radial"
C5: "CAP, CERM, 10 µF, 25 V, +/- 20%, X7R, 1206_190"
C6 C9: "CAP, CERM, 0.1 µF, 16 V, +/- 10%, X7R, 0603"
C7 C8: "CAP, CERM, 1 µF, 16 V, +/- 10%, X7R, 0603"
C10: "CAP, CERM, 1000 pF, 50 V, +/- 10%, X7R, 0603"
C11: "CAP, CERM, 4.7 µF, 16 V, +/- 10%, X7R, 0805"
C12: "CAP, AL, 1000µF, 25V, +/- 20%, Radial"
C13: "CAP, CERM, 10 µF, 16 V, +/- 10%, X5R, 0805"
C14: "CAP, AL, 2200µF, 16V, +/- 20%, Radial"
D1 D2 D3 D4 D5 D6 D7 D9 D10 D11 D12 D13 D14 D15 D18 D19 D20 D21 D22 D23 D24 D25 D26 D27 D28 D29 D30 D31 D32 D33 D34 D35 D36 D37 D38 D39 D40 D41 D42 D43 D44 D45 D48 D49 D50 D51 D52 D53 D54 D55 D56 D57 D58 D59 D60 D61 D62 D63 D64 D65 D66 D67 D68 D70 D71 D72 D73 D74 D75 D76 D77 D78 D79 D80 D81 D82 D83 D84 D85 D86 D87 D88 D89 D90 D91 D92 D93 D94 D95 D96 D97 D99 D100 D101 D102 D103 D104 D105 D107 D108 D110 D111 D112 D113 D114 D115: library part LED, "LED, White, 3500K, 80 CRI, SMD"
D8 D69 D98 D109: "Diode, Ultrafast, 200 V, 1 A, SMA"
D16 D17 D46 D47: "Diode, P-N, 1000V, 1A, 3.9x1.7x1.8mm"
D106: "Diode, Switching, 100 V, 0.2 A, SOD-123"
F1: library part "RST 1", "Fuse, 2 A, 250VAC/VDC, TH"
H1: "Heat Sink, TO-220, Vertical"
H2: library part Htsk_HAMF10T, "HEATSINK PFE1000F"
J1: "Terminal Block, 5.08 mm, 2x1, TH"
LOGO2 LOGO3: library part IEC_HighVoltage, "IEC 61010-1 High Voltage Warning"
LOGO4 LOGO5: library part IEC_HotSurface, "IEC 61010-1 Hot Surface Warning"
Logo6: library part LED_Warning, "LED Warning Symbol"
Q1: library part MOSFET_N_D2G1S3, "MOSFET, N-CH, xxV, xxxA, [PackageReference]"
R1 R8 R17 R31: library part Resistor, "RES, 0.25 ohm, 1%, 0.25W, 0805"
R6: "RES, 1.50 M, 1%, 0.125 W, 0805"
R7 R13 R26 R33: "RES, 806 k, 1%, 0.25 W, 1206"
R9: "RES, 1.40 M, 1%, 0.125 W, 0805"
R10 R14: "RES, 1.00 M, 1%, 0.25 W, 1206"
R11 R12: "RES, 2.00 M, 1%, 0.125 W, 0805"
R15: "RES, 200 k, 1%, 0.1 W, 0603"
R16: "RES, 10.0, 1%, 0.1 W, 0603"
R18 R22 R24 R25 R27 R29: "RES, 18.2, 1%, 0.25 W, 1206"
R19 R23: "RES, 30.1 k, 1%, 0.1 W, 0603"
R20 R34: library part Resistor
R21: "RES, 1.24 M, 1%, 0.125 W, 0805"
R28: "RES, 54.9 k, 1%, 0.1 W, 0603"
R30: "RES, 121 k, 1%, 0.1 W, 0603"
R32: "RES, 976 k, 1%, 0.125 W, 0805"
RECT-AC1 TP1 TP2 TP3 TP4 TP5 TP6 TP8 TP9 TP10 TP12 TP13 TP14 TP15: library part 1502-2, "Terminal, Turret, TH, Double"
RT1: "Thermistor NTC, 470k ohm, 3%, 0603"
RV1: library part Varistor_MetalOxide, "Varistor, 240VAC, 200VDC, 10mm, Radial"
TP7: "Test Point, Miniature, White, TH"
TP11: "Test Point, Miniature, Black, TH"
U1 U2 U4 U5: "Floating Switch for Offline AC Linear Direct Drive of LEDs with Low Ripple Current, DDA0008E (SOIC-8)"
U3: "Switch Controlled Direct Drive Linear Controller for Offline LED Drivers, D0013A (SOIC-13)"

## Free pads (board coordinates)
  round 300 / inner round 0 / far side round 300 hole 137.8 unplated: 0(-2000,0) 0(-2000,5846.46)

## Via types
v1: diameter 34, hole 16, Top Layer to Bottom Layer, 25 vias
v2: diameter 19.68, hole 7.87, Top Layer to Bottom Layer, tented both sides, 16 vias
v3: diameter 19.68, hole 7.87, Top Layer to Bottom Layer, 16 vias

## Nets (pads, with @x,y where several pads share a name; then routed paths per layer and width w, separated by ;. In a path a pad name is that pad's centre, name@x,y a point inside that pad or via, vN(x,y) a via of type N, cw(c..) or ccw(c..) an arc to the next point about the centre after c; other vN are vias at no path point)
GND: C1.2 C3.2 C5.2 C6.1 C8.1 C9.2 C10.2 C11.1 C13.2 D46.2 D47.2 R7.1 R13.1 R18.2 R20.1 R22.2 R23.1 R24.2 R25.2 R26.1 R27.2 R29.2 R30.1 R33.1 RT1.1 TP11.1 U3.6 | length 11721.9
  Top Layer w12: C11.1@-1665,925 -1700,925 -1710,935 -1805,935 -1925,1055 -2100,1055 -2170,985 -2170,285 -2085,200 -1700,200 -1355,-145 v1(-1310,-145) ; v1(-295,20) -250,20 -75,195 3635,195 3670,230 3670,1705 3650,1725 1693,1725 RT1.1@1675,1743
  Top Layer w20: C11.1@-1665,925 -1665,970 v1(-1650,985) ; v1(-1655,790) U3.6@-1592.72,790 ; C6.1@-1497,475 -1482,460 v1(-1450,460) -1450,503 C8.1@-1472,525 ; R30.1@-1447,575 -1385,575 v1(-1370,590) -1410,630 C13.2@-1410,640
  Top Layer w40: v1(-1825,5575) D47.2@-1764.96,5575 ; R33.1@-1792.91,1725 v1(-1735,1725) ; R26.1@-1792.91,2325 v1(-1735,2325) ; R13.1@-1792.91,2925 v1(-1735,2925) ; R7.1@-1792.91,3550 v1(-1735,3550) ; D46.2@-435.04,5575 v1(-375,5575)
  Bottom Layer w12: v1(-1310,-145) -430,-145 -295,-10 v1(-295,20)
  other v1: -1150,685 -1050,685 -1150,915 -1050,915
NetC2_1: C2.1 D8.1 R1.1 R6.2 TP1.1 U1.1 | length 1304.3
  Top Layer w20: R6.2@-1785,3950 -1785,3905 -1775,3895 U1.1@-1775,3857.28 -1737.28,3857.28 -1708.74,3828.74 D8.1@-1650,3828.74 -1481.26,3828.74 -1387.36,3922.64 C2.1@-1225,3922.64
  Top Layer w40: C2.1@-1225,3922.64 -1012.36,3922.64 -960,3975 TP1.1@-800,3975 R1.1@-640,3975
NetC2_2: C2.2 D48.2 D55.2 D69.2 TP3.1 U1.4 U1.9@-1850,3750 U2.8 | length 2372.9
  Top Layer w20: v2(-1926.77,3771.65) -1926.77,3818.23 -1925,3820 U1.4@-1925,3857.28 ; U2.8@-1775,3017.72 -1742.28,3017.72 -1713.74,3046.26 D69.2@-1650,3046.26 -1503.74,3046.26 -1430,3120 -1150,3120 -1110,3160 -1110,3280 -1225,3395 C2.2@-1225,3627.36
  Top Layer w40: C2.2@-1225,3627.36 -177.36,3627.36
  other v2: -1926.77,3728.35 -1773.23,3728.35 -1773.23,3771.65
  other v3: -1875.59,3728.35 -1824.41,3728.35 -1875.59,3771.65 -1824.41,3771.65
NetC4_1: C4.1 D69.1 R8.1 R9.2 TP4.1 U2.1 | length 1304.3
  Top Layer w20: R9.2@-1785,3325 -1785,3280 -1775,3270 U2.1@-1775,3232.28 -1737.28,3232.28 -1708.74,3203.74 D69.1@-1650,3203.74 -1481.26,3203.74 -1461.57,3223.43 C4.1@-1225,3223.43
  Top Layer w40: TP4.1@-800,3350 R8.1@-640,3350
  Bottom Layer w40: C4.1@-1225,3223.43 -926.57,3223.43 TP4.1@-800,3350
NetC4_2: C4.2 D77.2 D84.2 D98.2 TP6.1 U2.4 U2.9@-1850,3125 U4.8 | length 2862.5
  Top Layer w20: v2(-1926.77,3146.65) -1926.77,3193.23 -1925,3195 U2.4@-1925,3232.28 ; U4.8@-1775,2417.72 -1742.28,2417.72 -1713.74,2446.26 D98.2@-1650,2446.26 -1493.74,2446.26 -1425,2515 -1165,2515 -1110,2570 -1110,2725 -1225,2840 C4.2@-1225,3026.57
  Top Layer w40: C4.2@-1225,3026.57 -451.57,3026.57 -275,2850 -275,2450 -225,2400 -175,2400
  other v2: -1926.77,3103.35 -1773.23,3103.35 -1773.23,3146.65
  other v3: -1875.59,3103.35 -1824.41,3103.35 -1875.59,3146.65 -1824.41,3146.65
NetC5_1: C5.1 D106.1 U3.12 | length 653.3
  Top Layer w12: U3.12@-1807.28,640 -1760,640 -1710,690 -1710,790.24 -1625,875.24 -1625,966.16 -1615,976.16 -1615,995 -1645,1025 D106.1@-1699.47,1025
  Top Layer w20: C5.1@-1878.07,600.32 -1878.07,611.93 -1850,640 U3.12@-1807.28,640
NetC6_2: C6.2 U3.1 | length 81.5
  Top Layer w20: U3.1@-1592.72,540 -1592.72,514.72 C6.2@-1553,475
NetC7_1: C7.1 Q1.3 R18.1 R22.1 R24.1 R25.1 R27.1 R28.2 R29.1 TP10.1 | length 813.9
  Top Layer w25: TP10.1@-1400,950 -1400,865 -1392,857 C7.1@-1392,815 -1392,789 R28.2@-1392,765 -1320,765 -1312.09,757.09 R18.1@-1200,757.09 ; R29.1@-1000,842.91 -922.91,842.91 v1(-905,825)
  Bottom Layer w25: v1(-905,825) -830,825 -805,800 Q1.3@-587.5,800
NetC7_2: C7.2 D106.2 R16.1 | length 322.3
  Top Layer w20: D106.2@-1570.53,1025 -1555,1009.47 -1555,990 -1525,960 -1525,818 R16.1@-1500,793 -1478,815 C7.2@-1448,815
NetC8_2: C8.2 U3.2 | length 113.9
  Top Layer w20: U3.2@-1592.72,590 -1555,590 -1540,575 -1540,537 C8.2@-1528,525
NetC9_1: C9.1 R15.2 R19.2 U3.10 | length 477.1
  Top Layer w10: R15.2@-1953,875 -1925,847 -1925,753 C9.1@-1897,725
  Top Layer w20: C9.1@-1897,725 -1865,725 -1850,740 U3.10@-1807.28,740 -1767.99,740 -1747,760.99 R19.2@-1747,900
NetC10_1: C10.1 R15.1 R20.2 TP7.1 U3.9 | length 404.6
  Top Layer w20: TP7.1@-2050,950 -1930,950 -1897,917 R15.1@-1897,875 -1897,849 R20.2@-1897,825 -1897,798 C10.1@-1897,775 -1865,775 -1850,790 U3.9@-1807.28,790
NetC11_2: C11.2 U3.7 | length 88.2
  Top Layer w20: U3.7@-1592.72,840 -1592.72,867.28 -1585,875 C11.2@-1585,925
NetC12_1: C12.1 D98.1 R17.1 R21.2 TP8.1 U4.1 | length 1309.3
  Top Layer w20: R21.2@-1785,2725 -1785,2680 -1775,2670 U4.1@-1775,2632.28 -1737.28,2632.28 -1708.74,2603.74 D98.1@-1650,2603.74 -1326.26,2603.74 -1306.57,2623.43 C12.1@-1225,2623.43
  Top Layer w40: TP8.1@-795,2750 R17.1@-635,2750
  Bottom Layer w40: C12.1@-1225,2623.43 -921.57,2623.43 TP8.1@-795,2750
NetC12_2: C12.2 D97.2 D105.2 D109.2 TP12.1 U4.4 U4.9@-1850,2525 U5.8 | length 6549.1
  Top Layer w20: v2(-1926.77,2546.65) -1926.77,2593.23 -1925,2595 U4.4@-1925,2632.28 ; U5.8@-1775,1817.72 -1742.28,1817.72 -1713.74,1846.26 D109.2@-1650,1846.26 -1458.74,1846.26 -1380,1925 -1000,1925
  Top Layer w40: C12.2@-1225,2426.57 -1000,2201.57 -1000,1925 -1000,1760 -895,1655 -305,1655 -180,1530 -180,1000 -160,980 3250,980
  other v2: -1926.77,2503.35 -1773.23,2503.35 -1773.23,2546.65
  other v3: -1875.59,2503.35 -1824.41,2503.35 -1875.59,2546.65 -1824.41,2546.65
NetC13_1: C13.1 R11.1 R30.2 U3.3 | length 804.4
  Top Layer w20: U3.3@-1592.72,640 C13.1@-1490,640 ; R30.2@-1503,575 -1490,588 C13.1@-1490,640 ; R11.1@-990,525 -1260,525 -1315,580 -1315,635 -1375,695 -1445,695 -1465,675 -1465,665 C13.1@-1490,640
NetC14_1: C14.1 D109.1 R31.1 R32.2 TP13.1 U5.1 | length 1309.3
  Top Layer w20: R32.2@-1785,2125 -1785,2080 -1775,2070 U5.1@-1775,2032.28 -1737.28,2032.28 -1708.74,2003.74 D109.1@-1650,2003.74 -1581.1,2072.64 C14.1@-1225,2072.64
  Top Layer w40: TP13.1@-795,2150 R31.1@-635,2150
  Bottom Layer w40: C14.1@-1225,2072.64 -872.36,2072.64 TP13.1@-795,2150
NetC14_2: C14.2 D114.2 D115.2 Q1.2 R12.2 R34.1 TP15.1 U5.4 U5.9@-1850,1925 | length 4586.3
  Top Layer w20: v2(-1926.77,1946.65) -1926.77,1993.23 -1925,1995 U5.4@-1925,2032.28 ; v1(-905,750) -905,720 R12.2@-875,690
  Top Layer w40: Q1.2@-587.5,700 -500,700 -465,735 -465,935 -430,970 -360,970 -305,915 3250,915
  Bottom Layer w20: v1(-905,750) -861,750 -811,700 Q1.2@-587.5,700
  other v2: -1926.77,1903.35 -1773.23,1903.35 -1773.23,1946.65
  other v3: -1875.59,1903.35 -1824.41,1903.35 -1875.59,1946.65 -1824.41,1946.65
NetD1_1: D1.1 D9.1 R1.2 TP2.1 | length 1342.8
  Top Layer w40: R1.2@-560,3975 TP2.1@-400,3975 -400,4100 -275,4225 -275,4975 -200,5050 -175,5050
NetD1_2: D1.2 D2.1
NetD2_2: D2.2 D3.1
NetD3_2: D3.2 D4.1
NetD4_2: D4.2 D5.1
NetD5_2: D5.2 D6.1
NetD6_2: D6.2 D7.1
NetD7_2: D7.2 D31.1
NetD9_2: D9.2 D10.1
NetD10_2: D10.2 D11.1
NetD11_2: D11.2 D12.1
NetD12_2: D12.2 D13.1
NetD13_2: D13.2 D14.1
NetD14_2: D14.2 D15.1
NetD15_2: D15.2 D24.1
NetD16_2: D16.2 D46.1 F1.1 | length 299.2
  Top Layer w50: F1.1@-725,5700 D16.2@-725,5564.96 -640.04,5564.96 -630,5575 D46.1@-564.96,5575
NetD17_2: D17.2 D47.1 J1.2 RV1.1 | length 760
  Top Layer w50: D47.1@-1635.04,5575 -1565,5575 -1554.96,5564.96 D17.2@-1475,5564.96 -1374.96,5564.96 -1365.32,5555.31 RV1.1@-1247.64,5555.31
  Bottom Layer w50: RV1.1@-1247.64,5555.31 -1200,5602.95 J1.2@-1200,5900
NetD18_1: D18.1 D19.2
NetD18_2: D18.2 D39.1
NetD19_1: D19.1 D20.2
NetD20_1: D20.1 D21.2
NetD21_1: D21.1 D22.2
NetD22_1: D22.1 D23.2
NetD23_1: D23.1 D24.2
NetD25_1: D25.1 D26.2
NetD25_2: D25.2 D32.1
NetD26_1: D26.1 D27.2
NetD27_1: D27.1 D28.2
NetD28_1: D28.1 D29.2
NetD29_1: D29.1 D30.2
NetD30_1: D30.1 D31.2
